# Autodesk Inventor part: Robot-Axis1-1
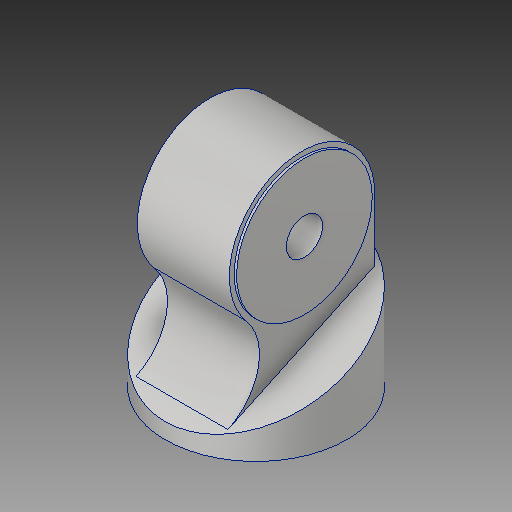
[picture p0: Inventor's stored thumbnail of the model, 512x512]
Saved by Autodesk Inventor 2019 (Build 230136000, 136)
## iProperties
Created: 2018-07
Part Number: Robot-Axis1-1
Material: Aluminum 6061
Description: 123456
Document SubType Name: Modeling
Designer: Power User
Mass: 5063.94 g
Surface Area: 1124.06 cm^2
Volume: 1875.53 cm^3
Density: 2.7 g/cm^3
Appearance: Aluminum - Flat
Title: GEAR
Author: Power User
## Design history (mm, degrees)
sketch "Sketch6"
  geometry: C1 r 75 at (0, 0); 1 further point
  constraints: 1 centre point, 1 coincident
  dimensions: "d44" = 150 diameter of C1
extrude "Extrusion5" new body sketch "Sketch6" distance "d45" = 100; taper "d46" = 0 deg
sketch "Sketch7"
  geometry: L1 (0, 75)-(0, -75) reference; L2 (0, 102.879)-(99.808, -111.161); L3 (0, 75)-(100, 75) reference; L4 (0, 102.879)-(-29.654, 102.879); L5 (-29.654, 102.879)-(-29.654, -111.161); L6 (-29.654, -111.161)-(99.808, -111.161); 2 further points
  constraints: 8 end point, 3 point on line, 2 perpendicular, 1 horizontal
  dimensions: "d47" = 25 deg angle of L1 L2; "d49" = 13 distance from line of L1 point (13, 75)
extrude "Extrusion6" sketch "Sketch7" stored distance "d50" = 200; taper "d51" = 0 deg
sketch "Sketch8"
  geometry: L1 (82.946, -75)-(13, 75) reference; L2 (128, -60)-(75.952, -60); L3 (13, 75)-(82.946, -75) reference; L4 (82.946, -75)-(0, -75) reference; L5 (0, -75)-(0, 75) reference; L6 (0, 75)-(13, 75) reference; L7 (0, 75)-(0, -75) reference; L8 (19.444, 61.181)-(75.952, -60); C1 r 56 at (128, 0); C2 r 15 at (128, 0); A1 r 60 centre (128, 0) between (128, -60) and (89.273, 45.828); A2 r 45 centre (60.228, 80.199) between (19.444, 61.181) and (89.273, 45.828); 1 further point
  constraints: 4 centre point, 4 end point, 4 point on circle, 3 tangent, 2 coincident, 2 point on line, 1 collinear, 1 horizontal
  dimensions: "d52" = 75 distance from line of L4 C1.centre; "d53" = 120 diameter of A1; "d54" = 112 diameter of C1; "d55" = 128 distance from line of C1.centre L7; "d56" = 45 radius of A2; "d57" = 30 diameter of C2
  node "Project Cut Edges2"
extrude "Extrusion7" join sketch "Sketch8" stored distance "d58" = 76; taper "d59" = 0 deg
extrude "Extrusion8" join sketch "Sketch8" stored distance "d60" = 80; taper "d61" = 0 deg
body "Solid2"
